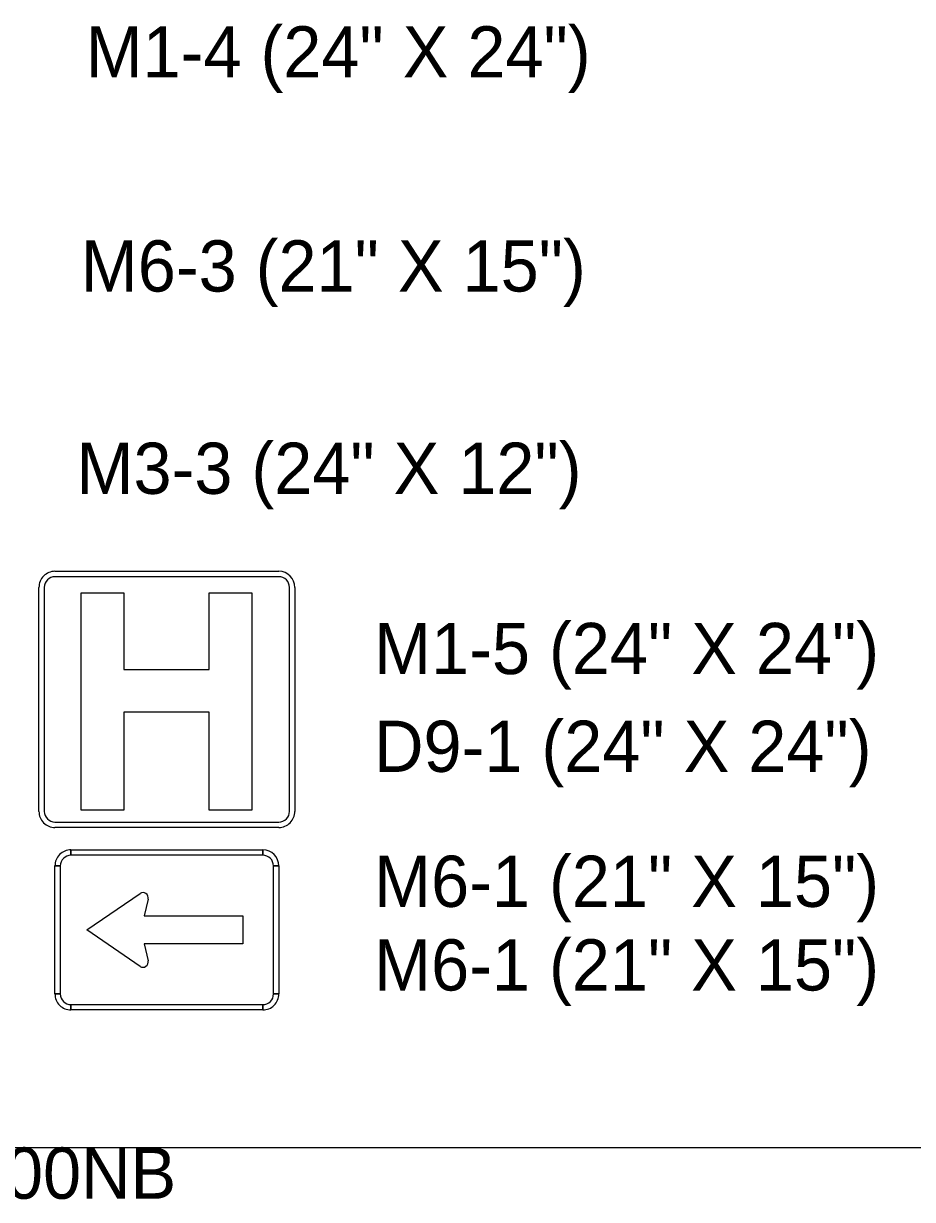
# Model space of a CAD drawing. Extents: x 1001568 to 1002149, y 1840825 to 1841423.
# Drawn here: x 1001925.78 to 1001932.72, y 1841269.06 to 1841278.25 of the extents above; entities that cross this region are included whole.
import ezdxf

# ---------------------------------------------------------------- set-up
doc = ezdxf.new("R2010")
doc.units = 0
for name, color, linetype in [('40', 7, 'Continuous'), ('R_No Plot', 7, 'Continuous'), ('SIGNS', 7, 'Continuous')]:
    doc.layers.add(name, color=color, linetype=linetype)

msp = doc.modelspace()

# ---------------------------------------------------------------- linework, layer by layer
at = {"layer": 'R_No Plot'}
msp.add_line((1001890.6501, 1841269.4691), (1001982.1327, 1841269.4691), dxfattribs=at)
at = {"layer": 'SIGNS'}
for p, q in [((1001926.0208, 1841273.9691), (1001927.7708, 1841273.9691)), ((1001926.0208, 1841273.9691), (1001927.7708, 1841273.9691)), ((1001927.7708, 1841273.9274), (1001926.0208, 1841273.9274)), ((1001925.8958, 1841272.0941), (1001925.8958, 1841273.8441)), ((1001925.8958, 1841272.0941), (1001925.8958, 1841273.8441)), ((1001925.9375, 1841273.8441), (1001925.9375, 1841272.0941)), ((1001926.2267, 1841272.1026), (1001926.2267, 1841273.8024)), ((1001926.2267, 1841273.8024), (1001926.5599, 1841273.8024)), ((1001926.2267, 1841272.1026), (1001926.2267, 1841273.8024)), ((1001926.2267, 1841273.8024), (1001926.5599, 1841273.8024)), ((1001926.5599, 1841273.8024), (1001926.5599, 1841273.2023)), ((1001926.5599, 1841273.8024), (1001926.5599, 1841273.2023)), ((1001927.2266, 1841273.2023), (1001927.2266, 1841273.8024)), ((1001927.2266, 1841273.8024), (1001927.5599, 1841273.8024)), ((1001927.2266, 1841273.2023), (1001927.2266, 1841273.8024)), ((1001927.2266, 1841273.8024), (1001927.5599, 1841273.8024)), ((1001927.5599, 1841273.8024), (1001927.5599, 1841272.1026)), ((1001927.5599, 1841273.8024), (1001927.5599, 1841272.1026)), ((1001927.8541, 1841272.0941), (1001927.8541, 1841273.8441)), ((1001927.8958, 1841273.8441), (1001927.8958, 1841272.0941)), ((1001927.8958, 1841273.8441), (1001927.8958, 1841272.0941)), ((1001926.5599, 1841273.2023), (1001927.2266, 1841273.2023)), ((1001926.5599, 1841273.2023), (1001927.2266, 1841273.2023)), ((1001927.2266, 1841272.869), (1001926.5599, 1841272.869)), ((1001926.5599, 1841272.869), (1001926.5599, 1841272.1026)), ((1001927.2266, 1841272.869), (1001926.5599, 1841272.869)), ((1001926.5599, 1841272.869), (1001926.5599, 1841272.1026)), ((1001927.2266, 1841272.1026), (1001927.2266, 1841272.869)), ((1001927.2266, 1841272.1026), (1001927.2266, 1841272.869)), ((1001926.5599, 1841272.1026), (1001926.2267, 1841272.1026)), ((1001926.5599, 1841272.1026), (1001926.2267, 1841272.1026)), ((1001927.5599, 1841272.1026), (1001927.2266, 1841272.1026)), ((1001927.5599, 1841272.1026), (1001927.2266, 1841272.1026)), ((1001926.0208, 1841272.0108), (1001927.7708, 1841272.0108)), ((1001927.7708, 1841271.9691), (1001926.0208, 1841271.9691)), ((1001927.7708, 1841271.9691), (1001926.0208, 1841271.9691)), ((1001926.1458, 1841271.7935), (1001926.1458, 1841271.7518)), ((1001927.6458, 1841271.7518), (1001927.6458, 1841271.7935)), ((1001926.0625, 1841271.6685), (1001926.0208, 1841271.6685)), ((1001927.7708, 1841271.6685), (1001927.7291, 1841271.6685)), ((1001926.2708, 1841271.1685), (1001926.686, 1841271.4537)), ((1001926.7489, 1841271.4091), (1001926.7187, 1841271.2779)), ((1001926.7187, 1841271.2779), (1001927.4895, 1841271.2779)), ((1001927.4895, 1841271.2779), (1001927.4895, 1841271.0591)), ((1001926.686, 1841270.8833), (1001926.2708, 1841271.1685)), ((1001927.4895, 1841271.0591), (1001926.7187, 1841271.0591)), ((1001926.7187, 1841271.0591), (1001926.7489, 1841270.9278)), ((1001926.0208, 1841270.6685), (1001926.0625, 1841270.6685)), ((1001927.7291, 1841270.6685), (1001927.7708, 1841270.6685)), ((1001926.1458, 1841270.5851), (1001926.1458, 1841270.5435)), ((1001927.6458, 1841270.5435), (1001927.6458, 1841270.5851))]:
    msp.add_line(p, q, dxfattribs=at)
for points in [[(1001926.1458, 1841271.7935), (1001927.6458, 1841271.7935), (1001927.6458, 1841271.7518), (1001926.1458, 1841271.7518), (1001926.1458, 1841271.7935), (1001926.1458, 1841271.7935)], [(1001926.0208, 1841270.6685), (1001926.0208, 1841271.6685), (1001926.0625, 1841271.6685), (1001926.0625, 1841270.6685), (1001926.0208, 1841270.6685), (1001926.0208, 1841270.6685)], [(1001927.7708, 1841271.6685), (1001927.7708, 1841270.6685), (1001927.7291, 1841270.6685), (1001927.7291, 1841271.6685), (1001927.7708, 1841271.6685), (1001927.7708, 1841271.6685)], [(1001927.6458, 1841270.5435), (1001926.1458, 1841270.5435), (1001926.1458, 1841270.5851), (1001927.6458, 1841270.5851), (1001927.6458, 1841270.5435), (1001927.6458, 1841270.5435)]]:
    msp.add_lwpolyline(points, close=True, dxfattribs=at)
for centre, radius, start, end in [((1001926.0208, 1841273.8441), 0.125, 89.99979, 180), ((1001926.0208, 1841273.8441), 0.125, 89.99979, 180), ((1001927.7708, 1841273.8441), 0.125, 0.00015, 89.99979), ((1001927.7708, 1841273.8441), 0.125, 0.00015, 89.99979), ((1001926.0208, 1841273.8441), 0.0833, 89.99979, 180), ((1001927.7708, 1841273.8441), 0.0833, 0.00015, 89.99979), ((1001926.0208, 1841272.0941), 0.125, 179.99973, 269.99994), ((1001926.0208, 1841272.0941), 0.125, 179.99973, 269.99994), ((1001926.0208, 1841272.0941), 0.0833, 179.99973, 269.99994), ((1001927.7708, 1841272.0941), 0.125, 269.99994, 0.00015), ((1001927.7708, 1841272.0941), 0.125, 269.99994, 0.00015), ((1001927.7708, 1841272.0941), 0.0833, 269.99994, 0.00015), ((1001926.1458, 1841271.6685), 0.125, 89.99979, 180), ((1001926.1458, 1841271.6685), 0.0833, 89.99979, 180), ((1001927.6458, 1841271.6685), 0.125, 0.00015, 89.99979), ((1001927.6458, 1841271.6685), 0.0833, 0.00015, 89.99979), ((1001926.7083, 1841271.4185), 0.0417, 347.04959, 122.27565), ((1001926.7083, 1841270.9185), 0.0417, 237.72408, 12.95014), ((1001926.1458, 1841270.6685), 0.125, 179.99973, 269.99994), ((1001926.1458, 1841270.6685), 0.0833, 179.99973, 269.99994), ((1001927.6458, 1841270.6685), 0.125, 269.99994, 0.00015), ((1001927.6458, 1841270.6685), 0.0833, 269.99994, 0.00015)]:
    msp.add_arc(centre, radius, start, end, dxfattribs=at)

# ---------------------------------------------------------------- texts
at = {"layer": '40'}
for s, p in [('M1-4 (24" X 24")', (1001926.2605, 1841277.826)), ('M6-3 (21" X 15")', (1001926.2228, 1841276.154)), ('M3-3 (24" X 12")', (1001926.1894, 1841274.5741)), ('M1-5 (24" X 24")', (1001928.5153, 1841273.1665)), ('D9-1 (24" X 24")', (1001928.5153, 1841272.4028)), ('M6-1 (21" X 15")', (1001928.5153, 1841271.3485)), ('M6-1 (21" X 15")', (1001928.5153, 1841270.6955)), ('SS-067-10-STA105+00NB', (1001920.6501, 1841269.0691))]:
    msp.add_text(s, height=0.4, rotation=0, dxfattribs=at).set_placement(p)

doc.saveas('drawing.dxf')
